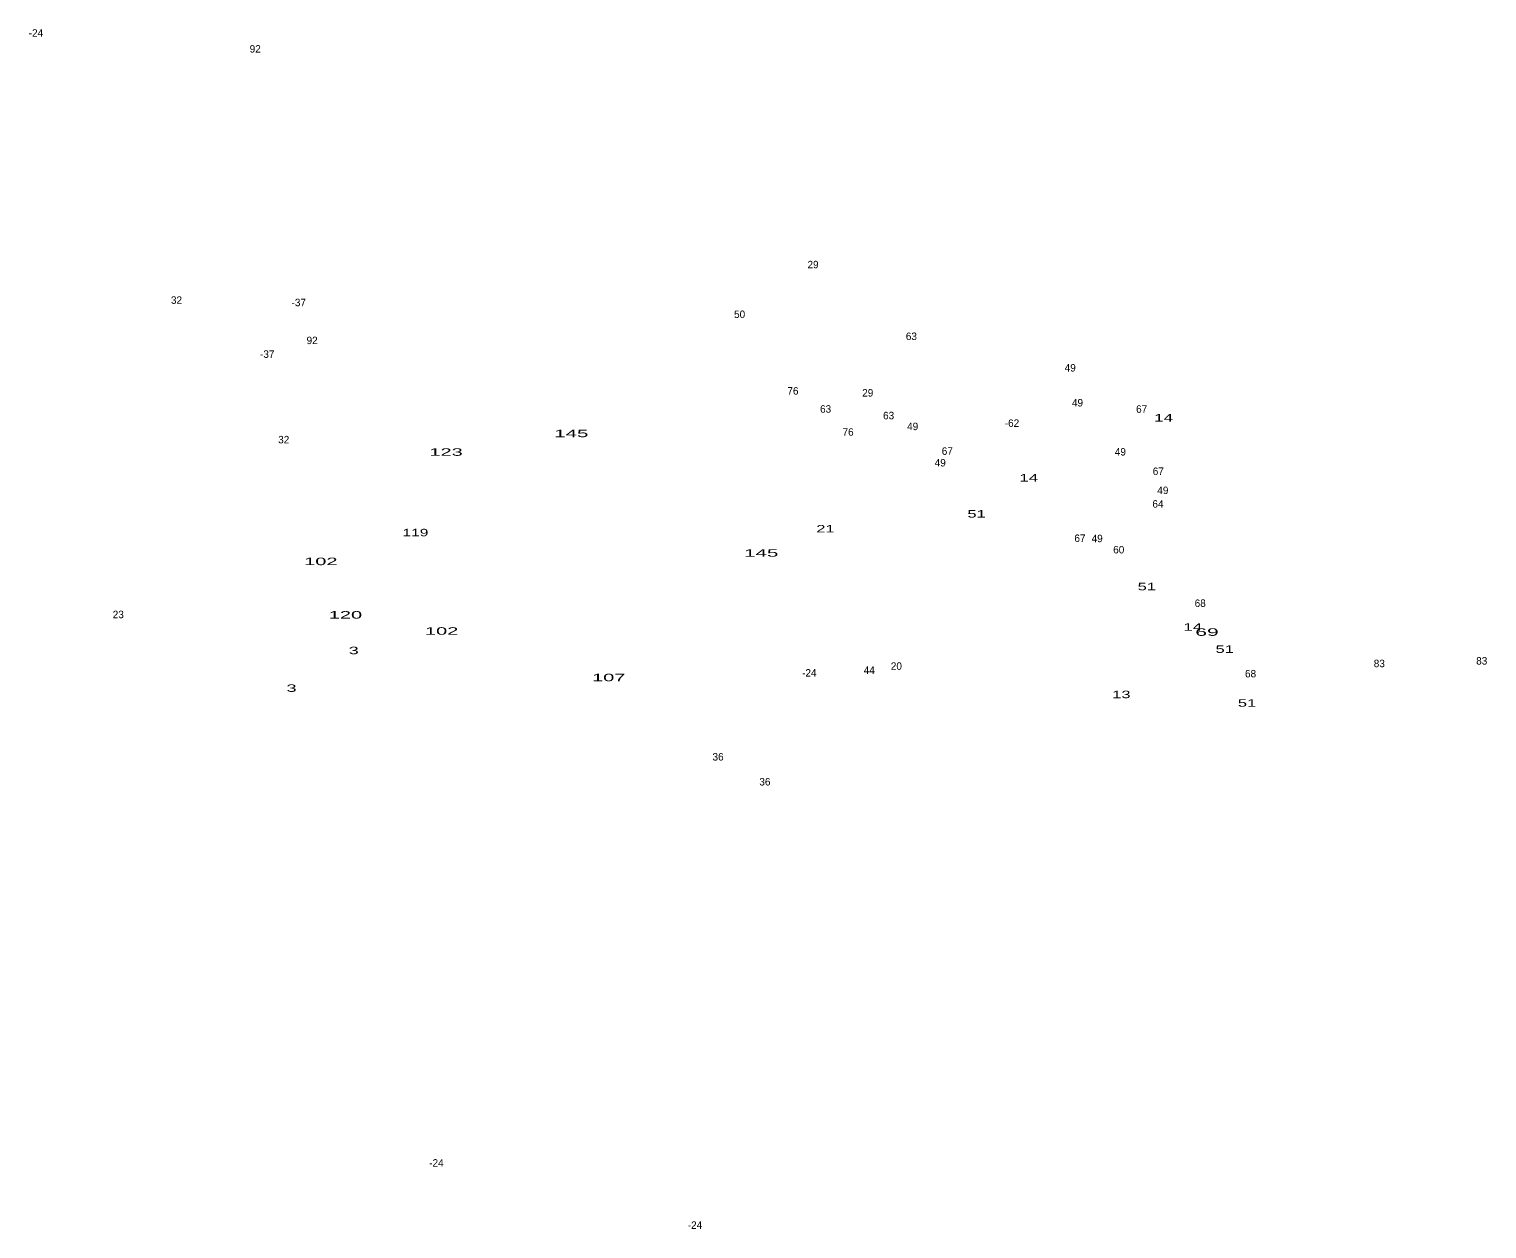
# Model space of a CAD drawing. Extents: x -672336 to -669011, y -998401 to -996613.
# Drawn here: x -669791 to -669011, y -997521 to -996879 of the extents above; entities that cross this region are included whole.
import ezdxf
from ezdxf.enums import TextEntityAlignment as Align

# ---------------------------------------------------------------- set-up
doc = ezdxf.new("R2010")
doc.units = 0
doc.header["$LTSCALE"] = 1.6
doc.layers.add('24', color=7, linetype='Continuous')

msp = doc.modelspace()

# ---------------------------------------------------------------- texts
at = {"layer": '24'}
for s, p in [('-24', (-669787.789, -996883.05)), ('92', (-669670.423, -996891.54)), ('29', (-669371.903, -997007.01)), ('32', (-669712.547, -997026.01)), ('-37', (-669647.141, -997027.29)), ('50', (-669411.191, -997033.61)), ('92', (-669639.973, -997047.6)), ('63', (-669319.263, -997045.4)), ('-37', (-669664.001, -997054.94)), ('49', (-669234.257, -997062.26)), ('76', (-669382.658, -997074.61)), ('29', (-669342.623, -997075.66)), ('63', (-669365.173, -997084.3)), ('49', (-669230.367, -997080.98)), ('67', (-669196.038, -997084.35)), ('63', (-669331.443, -997087.82)), ('49', (-669318.577, -997093.63)), ('-62', (-669265.43, -997091.89)), ('32', (-669655.167, -997100.72)), ('76', (-669353.148, -997096.63)), ('67', (-669300.028, -997106.85)), ('49', (-669207.417, -997107.23)), ('49', (-669303.817, -997113.08)), ('67', (-669187.128, -997117.63)), ('49', (-669184.697, -997127.85)), ('64', (-669187.307, -997135.14)), ('67', (-669229.058, -997153.48)), ('49', (-669219.827, -997153.62)), ('60', (-669208.287, -997159.63)), ('68', (-669164.683, -997188.27)), ('23', (-669743.707, -997194.3)), ('83', (-669014.027, -997219.13)), ('-24', (-669373.899, -997225.58)), ('44', (-669341.816, -997224.14)), ('20', (-669327.291, -997221.93)), ('68', (-669137.743, -997225.99)), ('83', (-669068.837, -997220.53)), ('36', (-669422.723, -997270.5)), ('36', (-669397.663, -997283.86)), ('-24', (-669573.449, -997487.89)), ('-24', (-669435.069, -997521.18))]:
    msp.add_text(s, height=4, dxfattribs=at).set_placement(p, align=Align.CENTER)
for s, width, p in [('14', 1.7, (-669184.303, -997089.02)), ('145', 2.05, (-669501.253, -997097.4)), ('123', 2, (-669568.287, -997107.36)), ('14', 1.7, (-669256.443, -997121.13)), ('51', 1.65, (-669284.377, -997140.46)), ('21', 1.65, (-669365.247, -997148.39)), ('119', 1.55, (-669584.669, -997150.46)), ('145', 2.05, (-669399.593, -997161.37)), ('102', 2, (-669635.314, -997165.89)), ('51', 1.65, (-669193.267, -997179.35)), ('120', 2, (-669622.134, -997194.51)), ('102', 2, (-669570.674, -997203.15)), ('14', 1.7, (-669168.653, -997200.97)), ('69', 2.1, (-669161.051, -997203.73)), ('3', 1.8, (-669617.711, -997213.58)), ('51', 1.65, (-669151.577, -997212.87)), ('3', 1.8, (-669650.971, -997233.73)), ('107', 2, (-669481.229, -997228.05)), ('13', 1.65, (-669206.887, -997237.12)), ('51', 1.65, (-669139.637, -997241.69))]:
    msp.add_text(s, height=4, dxfattribs=dict(at, width=width)).set_placement(p, align=Align.CENTER)

doc.saveas('drawing.dxf')
